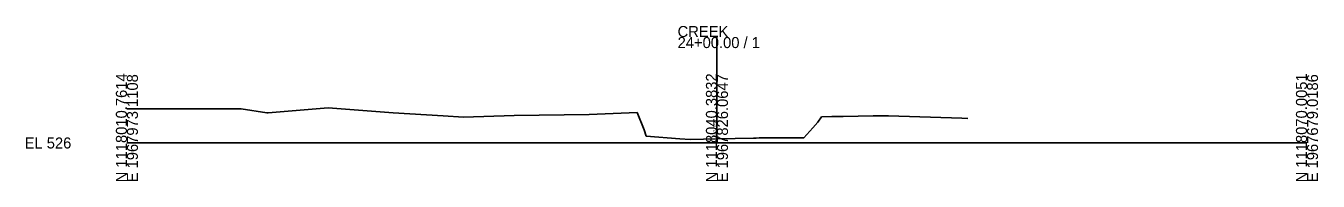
# Model space of a CAD drawing. Extents: x 9974 to 10303, y 9990 to 19550.
# Drawn here: x 9974.3 to 10302.8, y 13490.3 to 13529.8 of the extents above; entities that cross this region are included whole.
import ezdxf

# ---------------------------------------------------------------- set-up
doc = ezdxf.new("R2010")
doc.units = 0
for name, color, linetype in [('Level 10', 7, 'Continuous'), ('Level 60', 7, 'Continuous'), ('Level 63', 7, 'Continuous')]:
    doc.layers.add(name, color=color, linetype=linetype)

msp = doc.modelspace()

# ---------------------------------------------------------------- linework, layer by layer
at = {"layer": 'Level 60'}
for p, q in [((10000, 13508.64), (10008.08, 13508.65)), ((10008.08, 13508.65), (10029.04, 13508.64)), ((10029.04, 13508.64), (10035.58, 13507.69)), ((10035.58, 13507.69), (10035.91, 13507.65)), ((10035.91, 13507.65), (10051.2, 13508.97)), ((10051.2, 13508.97), (10067.67, 13507.65)), ((10067.67, 13507.65), (10080.39, 13506.94)), ((10080.39, 13506.94), (10085.61, 13506.53)), ((10085.61, 13506.53), (10098.41, 13507)), ((10098.41, 13507), (10117.55, 13507.25)), ((10117.55, 13507.25), (10129.75, 13507.78)), ((10129.75, 13507.78), (10131.53, 13503.31)), ((10175.67, 13505.26), (10176.6, 13506.68)), ((10176.6, 13506.68), (10179.17, 13506.71)), ((10179.17, 13506.71), (10182.05, 13506.77)), ((10182.05, 13506.77), (10189.71, 13506.93)), ((10189.71, 13506.93), (10193.63, 13506.94)), ((10193.63, 13506.94), (10212.23, 13506.3)), ((10212.23, 13506.3), (10213.8, 13506.21)), ((10131.53, 13503.31), (10132.02, 13501.72)), ((10172.09, 13501.34), (10174.34, 13503.81)), ((10174.34, 13503.81), (10175.67, 13505.26)), ((10132.02, 13501.72), (10140.53, 13501.04)), ((10140.53, 13501.04), (10143.19, 13500.86)), ((10143.19, 13500.86), (10150, 13501.02)), ((10150, 13501.02), (10159.31, 13501.25)), ((10159.31, 13501.25), (10159.95, 13501.26)), ((10159.95, 13501.26), (10160.76, 13501.27)), ((10160.76, 13501.27), (10172.09, 13501.34))]:
    msp.add_line(p, q, dxfattribs=at)
at = {"layer": 'Level 63'}
for p, q in [((10150, 13500), (10150, 13526.92)), ((10000, 13500), (10150, 13500)), ((10150, 13500), (10300, 13500))]:
    msp.add_line(p, q, dxfattribs=at)

# ---------------------------------------------------------------- texts
at = {"layer": 'Level 10'}
msp.add_text('527.022', height=0.8, rotation=90, dxfattribs=at).set_placement((10149.9, 13501.52))
at = {"layer": 'Level 63'}
for s, p in [('CREEK', (10140, 13526.92)), ('24+00.00 / 1', (10140, 13524.12)), ('EL 526', (9974, 13498.6))]:
    msp.add_text(s, height=2.8, dxfattribs=at).set_placement(p)
for s, p in [('N 1118010.7614', (10000, 13490)), ('E 1967973.1108', (10002.8, 13490)), ('N 1118040.3832', (10150, 13490)), ('E 1967826.0647', (10152.8, 13490)), ('N 1118070.0051', (10300, 13490)), ('E 1967679.0186', (10302.8, 13490))]:
    msp.add_text(s, height=2.8, rotation=90, dxfattribs=at).set_placement(p)

doc.saveas('drawing.dxf')
